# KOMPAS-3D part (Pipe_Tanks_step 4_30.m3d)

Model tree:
1. X Axis
2. Y Axis
3. Z Axis
     Òîëùèíà ñòåíêè 1 = 1

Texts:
  Pipe Dn 20
  Steel ASTM A295
  Three Point Plane
  Plane at Angle
  Line and Point Plane
  Axis through Two Vertices
  Axis of Feature
  Axis of Conical Surface
  Axis through Edge
  Trim by Surface
  Trim by Sketch
  Feature with No History
  Intersection Axis of Two Planes
  Two Line Plane
  Line and Face Plane
  Bend by line
  Hole in sheet body
  Cut in sheet body
  Point in CM
  Linear Dimension from Line to Point
  Surface Finish Symbol
  Geometric Tolerance Symbol
  Leader #1
  Leader #2
  Leader #3
  Shape Deviations and Datum
  Node point number
  Mark of coordination axis
  Node point designation
  Mark/Reference designation with leader
  Mark/reference designation on line
  Mark/Reference designation without leader
  Plane of section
